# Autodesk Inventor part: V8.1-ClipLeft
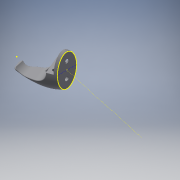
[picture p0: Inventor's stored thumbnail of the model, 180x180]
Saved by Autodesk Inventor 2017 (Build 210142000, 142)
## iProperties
Created: 2015-10
Part Number: V8.1-ClipLeft
Material: Generic
Document SubType Name: Modeling
Designer: Luke Denby
Density: 1 g/cm^3
Appearance: Default
Author: Luke Denby
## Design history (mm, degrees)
workplane "Work Plane3"
sketch "Front"
  geometry: L1 (15, -25)-(-15, -25); L2 (-15, -25)-(-15, 25); L3 (-15, 25)-(15, 25); L4 (15, 25)-(15, -25); L5 (0, -25)-(0, 25); L6 (-15, 0)-(15, 0); 2 further points
  constraints: 12 end point, 6 midpoint, 2 parallel, 2 perpendicular, 1 coincident, 1 horizontal, 4 other
  dimensions: "d3" = 30 distance of L6.start L6.end; "d8" = 50 distance of L5.start L5.end
sketch "End" dims "d15" = 8, "d16" = 8
  geometry: L1 (10, 17)-(10, -13); L2 (24, 0)-(-0.308, 0); 6 further points; 1 other entity
  constraints: 4 end point, 4 point on line, 1 horizontal, 1 vertical, 6 other
sketch "Sides" dims "d40" = 16 (derived)
sketch "Top"
node "3D Sketch8"
sketch "Bottom"
loft "Loft1" sketch "Bottom" dims "d17" = 0, "d18" = 90 deg, "d19" = 0, "d20" = 90 deg, "d21" = 0, "d22" = 90 deg, "d23" = 0, "d24" = 90 deg, "d25" = 0, "d26" = 90 deg, "d53" = 0, "d54" = 90 deg
fillet "Fillet3" dims "d29" = 6
sketch "Angle Line"
  geometry: L1 (151, -33)-(0, 0)
  constraints: 2 end point
workplane "Work Plane8"
node "3D Sketch11"
sketch "Sketch14"
  geometry: L1 (-1.282, 2.515)-(1.536, 2.515); L2 (1.536, 2.515)-(1.536, -1.569); L3 (1.536, -1.569)-(-1.282, -1.569); L4 (-1.282, -1.569)-(-1.282, 2.515); 1 further point
  constraints: 2 other
extrude "Version Number" cut sketch "Sketch14" distance "d57" = 2; taper "d58" = 0 deg
sketch "Sketch16"
  geometry: 1 further point
workplane "Work Plane10"
sketch "Sketch20"
  geometry: L1 (-24, -28)-(28, -28); 1 further point
  constraints: 2 end point, 1 horizontal
node "Clip End Work Plane"
sketch "Sketch25"
  geometry: 1 further point
sketch "Clip Front"
  geometry: L1 (9, 7.5)-(39, 7.5); L2 (24, 20)-(24, -5); 4 further points
  constraints: 4 end point, 3 midpoint, 1 coincident, 1 horizontal, 1 point on line, 1 vertical, 7 other
  dimensions: "d73" = 30 distance of L1.start point (39, 7.5); "d74" = 25 distance of L2.end L2.start
sketch "Clip Sides"
sketch "Clip Top"
  geometry: L1 (0, 15)-(-40, 11); L2 (-40, 11)-(-61.841, -9.206); L3 (-61.841, -9.206)-(-53.29, -32.698) reference; 2 further points
  constraints: 1 coincident, 3 other
sketch "Sketch24"
  geometry: L1 (0, 15)-(0, -15); 1 further point
  constraints: 2 end point, 1 vertical, 1 vertical alignment, 1 other
sketch "Clip Bottom"
  geometry: L1 (0, -15)-(-34.83, -29.214); L2 (-34.83, -29.214)-(-53.29, -32.698); L3 (0, 15)-(0, -15) reference; 2 further points
  constraints: 1 coincident, 3 other
loft "Clip" sketch "Clip Bottom" dims "d75" = 0, "d76" = 90 deg, "d77" = 0, "d78" = 90 deg, "d79" = 0, "d80" = 90 deg, "d81" = 0, "d82" = 90 deg, "d83" = 0, "d84" = 90 deg, "d85" = 0, "d86" = 90 deg
  node "Edges1"
workplane "Work Plane12"
sketch "Clip Hole Sketch"
  geometry: L1 (39, 0)-(9, 0) reference; L2 (24, -194.931)-(24, 89.069); L3 (14, 8.871)-(14, -26.129); L4 (34, 8.871)-(34, -26.129); A1 r 10 centre (24, -26.129) between (24, -36.129) and (14, -26.129); A2 r 10 centre (24, 8.871) between (24, 18.871) and (14, 8.871); 6 further points
  constraints: 6 end point, 6 point on circle, 6 point on line, 4 tangent, 2 centre point, 1 midpoint, 1 vertical, 2 other
  dimensions: "d88" = 20 diameter of A1; "d141" = 20 diameter of A2; "d142" = 55 distance of A2.start A1.start; "d145" = 30 distance of A1.centre point (24, -56.129)
sketch "Sketch27"
  geometry: C1 r 2.25 at (0, -12); 1 further point
  constraints: 1 centre point, 1 vertical alignment
  dimensions: "d93" = 4.5 diameter of C1; "d95" = 12 distance of point (0, 0) C1.centre
extrude "Screw Holes Handle" cut sketch "Sketch27" distance "d97" = 12; taper "d99" = 0 deg; dims "d98" = 20, "d100" = 0
node "Counterbore Workplane"
sketch "Sketch28"
  geometry: C1 r 4.5 at (0, -12); C2 r 4.5 at (0, 12); 1 further point
  constraints: 2 centre point, 2 vertical alignment
  dimensions: "d102" = 9 diameter of C2; "d103" = 12 distance of point (0, 0) C1.centre; "d104" = 12 distance of C2.centre point (0, 0); "d128" = 9 diameter of C1
extrude "Counterbore" cut sketch "Sketch28" distance "d180" = 15; taper "d181" = 0 deg
sketch "Sketch29"
  geometry: C1 r 2.85 at (0, -12); C2 r 2.85 at (0, 12); 1 further point
  constraints: 2 centre point, 2 vertical alignment
  dimensions: "d107" = 5.7 diameter of C1; "d109" = 12 distance of point (0, 0) C1.centre; "d197" = 5.7 diameter of C2 (derived); "d198" = 12 distance of C2.centre point (0, 0)
extrude "Screw Holes Clip" cut sketch "Sketch29" stored distance "d110" = 20; taper "d111" = 0 deg
workplane "Work Plane14"
fillet "Fillet8" dims "d125" = 4
extrude "Clip Hole" cut sketch "Clip Hole Sketch" stored distance "d143" = 10; taper "d144" = 0 deg
fillet "Fillet14" dims "d146" = 1
sketch "Handle Cut Off Sketch"
  geometry: L1 (-170, -40)-(0, -40); L2 (0, -40)-(0, 40); L3 (0, 40)-(-170, 40); L4 (-170, 40)-(-170, -40); L5 (-170, -40)-(0, 40); L6 (0, -40)-(-170, 40); 4 further points
  constraints: 12 end point, 3 midpoint, 2 parallel, 1 horizontal, 1 horizontal alignment, 1 perpendicular, 1 point on line
  dimensions: "d112" = 80 distance of L3.end L1.start; "d113" = 170 distance of L2.end L3.end
sketch "Clip Cut Off Sketch"
  geometry: L1 (74, 41)-(0, 41); L2 (0, 41)-(0, -41); L3 (0, -41)-(74, -41); L4 (74, -41)-(74, 41); L5 (74, 41)-(0, -41); L6 (0, 41)-(74, -41); L7 (-165.272, 0)-(74, 0); L8 (-170, -40)-(0, -40) reference; L9 (0, -40)-(0, 40) reference; 4 further points
  constraints: 14 end point, 4 midpoint, 2 parallel, 1 horizontal, 1 perpendicular, 1 point on line
  dimensions: "d133" = 74 distance of L2.end L3.end; "d134" = 82 distance of L3.end L1.start; "d136" = 40 distance between parallel lines of L7 L8
workplane "Work Plane15"
workplane "Work Plane16"
sketch "Slot Top"
  geometry: L1 (24, -216.564)-(24, 8.278) reference; L2 (38.5, -26.129)-(9.5, -26.129); L3 (38.5, -15.129)-(9.5, -15.129); L4 (38.5, -26.129)-(38.5, -15.129); L5 (9.5, -26.129)-(9.5, -15.129); A1 r 14.5 centre (24, -26.129) between (9.5, -26.129) and (38.5, -26.129); A2 r 14.5 centre (24, -15.129) between (38.5, -15.129) and (9.5, -15.129); 1 further point
  constraints: 8 end point, 4 point on circle, 2 centre point, 2 midpoint, 1 horizontal, 1 perpendicular, 1 point on line
  dimensions: "d154" = 29 diameter of A2; "d155" = 29 diameter of A1; "d156" = 40 dimension on A2 A1
sketch "Slot Bottom"
  geometry: L1 (24, -42.379)-(24, 3.621); L2 (7.75, -26.129)-(7.75, -12.629); L3 (7.75, -26.129)-(39.868, -26.129); L4 (7.75, -12.629)-(40.25, -12.629); L5 (40.25, -26.129)-(40.25, -12.629); A1 r 16.25 centre (24, -26.129) between (7.75, -26.129) and (40.25, -26.129); A2 r 16.25 centre (24, -12.629) between (40.25, -12.629) and (7.75, -12.629); 2 further points
  constraints: 10 end point, 6 point on circle, 3 point on line, 2 centre point, 2 horizontal, 2 tangent, 1 coincident, 1 vertical, 1 vertical alignment
  dimensions: "d157" = 32.5 diameter of A1; "d158" = 32.5 diameter of A2; "d159" = 46 distance of L1.end L1.start
loft "Bottle Slot" sketch "Slot Bottom" dims "d160" = 0, "d161" = 90 deg, "d162" = 0, "d163" = 90 deg
sketch "Sketch39"
  geometry: C1 r 34.655 at (0, 0); 1 further point
  constraints: 1 centre point
extrude "Extrusion18" cut sketch "Sketch39" distance "d170" = 40; taper "d171" = 0 deg
fillet "Fillet17" dims "d172" = 10
workplane "Work Plane17"
sketch "Sketch40"
  geometry: C1 r 2.5 at (-10, -10); 2 further points
  constraints: 1 centre point, 1 horizontal alignment
  dimensions: "d176" = 5 diameter of C1; "d228" = 10 horizontal distance of point (0, 0) C1.centre; "d229" = 10 horizontal distance of point (0, 0) C1.centre
extrude "Threaded Hole" cut sketch "Sketch40" distance "d178" = 50; taper "d179" = 0 deg
sketch "Sketch41"
  geometry: C1 r 6 at (-10, -10); C2 r 1.65 at (-10, -10); 3 further points
  constraints: 3 coincident, 2 centre point, 2 other
  dimensions: "d183" = 12 diameter of C1; "d184" = 3.3 diameter of C2
extrude "Collar" join sketch "Sketch41" stored distance "d186" = 15; taper "d187" = 0 deg
fillet "Collar Fillet" dims "d251" = 2
workplane "Work Plane18"
sketch "Sketch45"
  geometry: C1 r 2.5 at (-10, -10) reference; C2 r 3.3 at (-10, -10); 1 further point
  constraints: 1 centre point, 1 coincident
  dimensions: "d215" = 6.6 diameter of C2
extrude "Threaded Clearance Hole" cut sketch "Sketch45" stored distance "d216" = 28; taper "d217" = 0 deg
fillet "Collar Inner Fillet" dims "d252" = 0.8
fillet "Fillet20" dims "d219" = 0.9
fillet "Fillet22" dims "d221" = 1
sketch "Sketch46"
  geometry: C1 r 3.3 at (-10, -10) reference; C2 r 4.3 at (-10, -10); 1 further point
  constraints: 1 centre point, 1 coincident
  dimensions: "d222" = 8.6 diameter of C2
extrude "Spring Burrow" cut sketch "Sketch46" distance "d223" = 8; taper "d224" = 0 deg
extrude "Handle Cut Off" cut sketch "Handle Cut Off Sketch" stored distance "d230" = 5; taper "d231" = 0 deg
sketch "Sketch49"
  geometry: C1 r 2.8 at (0, 12); 1 further point
  constraints: 1 centre point, 1 vertical alignment
  dimensions: "d232" = 12 distance of C1.centre point (0, 0); "d233" = 5.6 diameter of C1
extrude "Countersunk Screw Hole Clip" cut sketch "Sketch49" distance "d234" = 4; taper "d235" = 0 deg
extrude "Neatening Sketch" cut sketch "Slot Top" distance "d239" = 10; taper "d240" = 0 deg
sketch "Sketch50"
  geometry: L1 (0, 0)-(-41, 0); C1 r 3.3 at (-10, 7); C2 r 2.5 at (-10, -10) reference
  constraints: 2 end point, 1 centre point, 1 horizontal, 1 vertical alignment
  dimensions: "d243" = 6.6 diameter of C1; "d246" = 7 distance from line of L1 C1.centre
extrude "Locating Pin Hole" cut sketch "Sketch50" distance "d247" = 12; taper "d249" = 0 deg; dims "d248" = 8, "d250" = 0
sketch "Clip R+L Cutoff Sketch"
  geometry: L1 (4, 0)-(70, 0); L2 (70, 0)-(70, -35); L3 (70, -35)-(0, -35); L4 (0, -35)-(0, 0); L5 (0, 0)-(0, 35); L6 (0, 35)-(70, 35); L7 (70, 35)-(70, 0); L8 (4, 0)-(4, 35); L9 (0, 0)-(70, 0); L10 (70, 1)-(4, 1)
  constraints: 21 end point, 8 perpendicular, 3 point on line, 2 horizontal, 1 vertical
  dimensions: "d190" = 70 distance between parallel lines of L4 L2; "d191" = 35 distance of L3.end L4.end; "d192" = 35 distance between parallel lines of L6 L1; "d236" = 4 distance between parallel lines of L8 L5; "d238" = 1 distance between parallel lines of L10 L1
sketch "Sketch51"
  geometry: C1 r 3.3 at (-10, 7) reference; C2 r 3.55 at (-10, 7); 1 further point
  constraints: 1 centre point, 1 coincident
  dimensions: "d253" = 7.1 diameter of C2
extrude "Locating Pin Clearence Hole" cut sketch "Sketch51" distance "d254" = 12; taper "d255" = 0 deg
extrude "Extrusion39" cut sketch "Clip R+L Cutoff Sketch" stored distance "d256" = 10; taper "d257" = 0 deg
chamfer "Chamfer1" distance "d258" = 3.5; stored, may be unused: second distance "d259" = 2, angle "d260" = 45 deg
body "Solid2"
node "Projected Loop1"
other parameters: "d46" = 90 deg, "d69" = 55, "d72" = 20 deg, "d87" = 90 deg, "d152" = 8, "d153" = -26, "d175" = 28, "d189" = 16
